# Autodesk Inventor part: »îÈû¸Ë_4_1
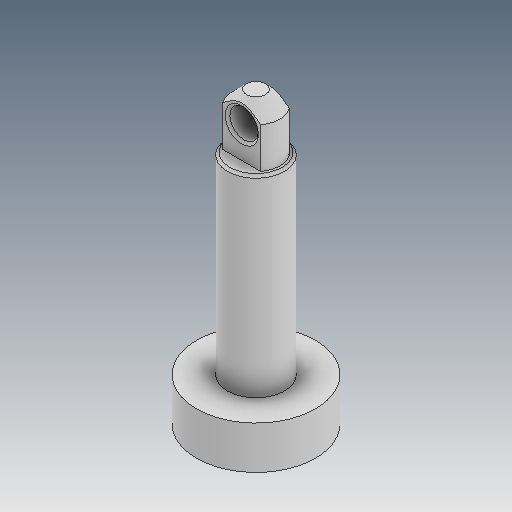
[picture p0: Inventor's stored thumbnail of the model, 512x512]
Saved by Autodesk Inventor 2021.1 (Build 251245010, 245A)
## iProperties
Created: 2019-04
Part Number: »îÈû¸Ë_4_1
Material: Ogólny
Document SubType Name: Modeling
Designer: user
Density: 1 g/cm^3
Appearance: Domyślna
Author: user
Revision Number: ÈÎºÎ
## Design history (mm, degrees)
feature "ÊäÈë1"
node "Bryła1"
